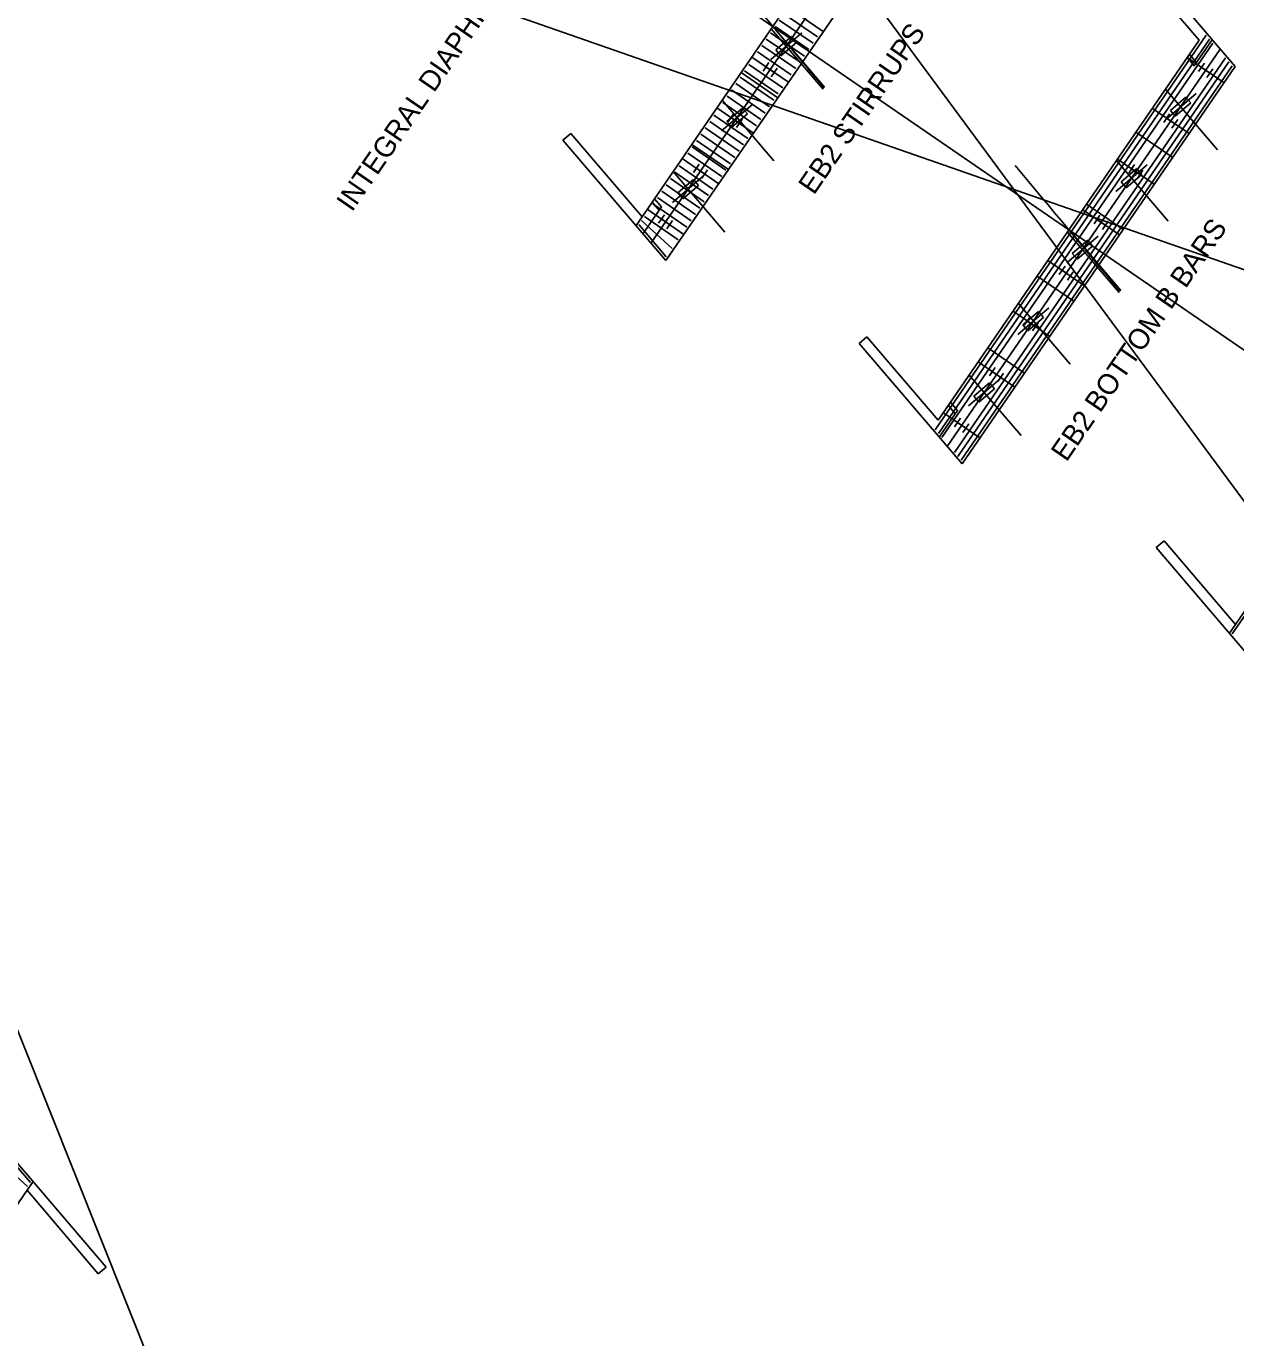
# Model space of a CAD drawing. Extents: x 2378999 to 2381348, y 331302 to 333122.
# Drawn here: x 2379130.1 to 2379248, y 331490.3 to 331618.1 of the extents above; entities that cross this region are included whole.
import ezdxf

# ---------------------------------------------------------------- set-up
doc = ezdxf.new("R2010")
doc.units = 0
for name, color, linetype in [('Arrowhead Terminators', 7, 'Continuous'), ('Arrowhead Terminators CELL', 7, 'Continuous'), ('Dimension Lines', 7, 'Continuous'), ('Dimension Lines CELL', 7, 'Continuous'), ('Mis Work Point CELL', 7, 'Continuous'), ('P_SMU_Bent_Cap', 7, 'Continuous'), ('P_SMU_D_Deck_Outline', 7, 'Continuous'), ('P_SMU_Girder_Concrete', 7, 'Continuous'), ('P_SMU_Mis_L_Lines', 7, 'Continuous'), ('P_SMU_Mis_Long_Chord', 7, 'Continuous'), ('P_SMU_Rebar_B_Bar', 7, 'Continuous'), ('Plan Sheet CELL', 7, 'Continuous'), ('Rebar Lines', 7, 'Continuous'), ('Sup Concrete Slab Lines', 7, 'Continuous')]:
    doc.layers.add(name, color=color, linetype=linetype)

msp = doc.modelspace()

# ---------------------------------------------------------------- linework, layer by layer
at = {"layer": 'Arrowhead Terminators'}
for p, q in [((2379218.72, 331578.81), (2379245.14, 331617.26)), ((2379219.04, 331578.43), (2379245.46, 331616.89)), ((2379219.37, 331578.04), (2379245.79, 331616.49)), ((2379247.02, 331615.05), (2379220.6, 331576.6)), ((2379247.36, 331614.66), (2379220.94, 331576.2)), ((2379247.68, 331614.28), (2379221.26, 331575.83)), ((2379247.69, 331558.9), (2379274.11, 331597.35))]:
    msp.add_line(p, q, dxfattribs=at)
at = {"layer": 'Arrowhead Terminators CELL'}
msp.add_line((2379247.99, 331559.83), (2379247.4, 331558.98), dxfattribs=at)
at = {"layer": 'Dimension Lines'}
for p, q in [((2379316.62, 331479.98), (2379154.62, 331699.5)), ((2379368.09, 331552.83), (2379115.15, 331641.03)), ((2379203.53, 331618.75), (2379206.83, 331616.48)), ((2379203.96, 331619.36), (2379207.25, 331617.1)), ((2379202.68, 331617.51), (2379205.98, 331615.24)), ((2379203.11, 331618.13), (2379206.4, 331615.86)), ((2379201.83, 331616.27), (2379205.13, 331614.01)), ((2379202.26, 331616.89), (2379205.55, 331614.63)), ((2379200.56, 331614.42), (2379203.86, 331612.15)), ((2379201.41, 331615.66), (2379204.7, 331613.39)), ((2379199.71, 331613.18), (2379203.01, 331610.92)), ((2379200.13, 331613.8), (2379203.43, 331611.54)), ((2379198.86, 331611.95), (2379202.16, 331609.68)), ((2379199.28, 331612.56), (2379202.58, 331610.3)), ((2379198.01, 331610.71), (2379201.31, 331608.44)), ((2379198.43, 331611.33), (2379201.73, 331609.06)), ((2379197.16, 331609.47), (2379200.46, 331607.21)), ((2379196.31, 331608.24), (2379199.61, 331605.97)), ((2379196.74, 331608.86), (2379200.03, 331606.59)), ((2379216.61, 331301.94), (2379094.44, 331607.27)), ((2379195.46, 331607), (2379198.76, 331604.74)), ((2379195.89, 331607.62), (2379199.18, 331605.35)), ((2379194.61, 331605.76), (2379197.91, 331603.5)), ((2379195.04, 331606.38), (2379198.33, 331604.12)), ((2379193.76, 331604.53), (2379197.06, 331602.26)), ((2379192.91, 331603.29), (2379196.21, 331601.03)), ((2379193.34, 331603.91), (2379196.64, 331601.65)), ((2379192.06, 331602.06), (2379195.36, 331599.79)), ((2379192.49, 331602.67), (2379195.79, 331600.41)), ((2379191.21, 331600.82), (2379194.51, 331598.55)), ((2379191.64, 331601.44), (2379194.94, 331599.17)), ((2379193.09, 331596.48), (2379190.09, 331599.19)), ((2379190.37, 331599.58), (2379193.66, 331597.32)), ((2379192.51, 331595.65), (2379189.82, 331598.8)), ((2379127.83, 331508.56), (2379130.52, 331505.42)), ((2379127.26, 331507.73), (2379130.25, 331505.02))]:
    msp.add_line(p, q, dxfattribs=at)
at = {"layer": 'Dimension Lines CELL'}
msp.add_line((2379340.37, 331523.67), (2379157.06, 331649.61), dxfattribs=at)
at = {"layer": 'Mis Work Point CELL'}
for p, q in [((2379191.02, 331597.01), (2379217.64, 331635.75)), ((2379219.89, 331577.17), (2379246.51, 331615.91))]:
    msp.add_line(p, q, dxfattribs=at)
at = {"layer": 'P_SMU_Bent_Cap'}
for p, q in [((2379205.73, 331617.5), (2379202.69, 331614.9)), ((2379244.17, 331611.6), (2379241.13, 331609)), ((2379200.94, 331610.53), (2379197.9, 331607.93)), ((2379239.38, 331604.63), (2379236.34, 331602.04)), ((2379196.15, 331603.56), (2379193.11, 331600.96)), ((2379234.6, 331597.67), (2379231.56, 331595.07)), ((2379229.81, 331590.7), (2379226.77, 331588.1)), ((2379225.02, 331583.73), (2379221.98, 331581.13))]:
    msp.add_line(p, q, dxfattribs=at)
at = {"layer": 'P_SMU_D_Deck_Outline'}
for p, q in [((2379204.72, 331617.13), (2379203.2, 331615.83)), ((2379205.21, 331616.56), (2379204.72, 331617.13)), ((2379203.69, 331615.26), (2379203.2, 331615.83)), ((2379205.21, 331616.56), (2379203.69, 331615.26)), ((2379243.17, 331611.24), (2379241.65, 331609.94)), ((2379243.66, 331610.67), (2379242.13, 331609.37)), ((2379243.66, 331610.67), (2379243.17, 331611.24)), ((2379199.94, 331610.17), (2379198.42, 331608.87)), ((2379200.42, 331609.6), (2379198.9, 331608.3)), ((2379200.42, 331609.6), (2379199.94, 331610.17)), ((2379242.13, 331609.37), (2379241.65, 331609.94)), ((2379198.9, 331608.3), (2379198.42, 331608.87)), ((2379238.38, 331604.27), (2379236.86, 331602.97)), ((2379238.87, 331603.7), (2379238.38, 331604.27)), ((2379195.15, 331603.2), (2379193.63, 331601.9)), ((2379195.64, 331602.63), (2379195.15, 331603.2)), ((2379237.35, 331602.4), (2379236.86, 331602.97)), ((2379238.87, 331603.7), (2379237.35, 331602.4)), ((2379194.12, 331601.33), (2379193.63, 331601.9)), ((2379195.64, 331602.63), (2379194.12, 331601.33)), ((2379233.59, 331597.3), (2379232.07, 331596)), ((2379234.08, 331596.73), (2379232.56, 331595.43)), ((2379234.08, 331596.73), (2379233.59, 331597.3)), ((2379232.56, 331595.43), (2379232.07, 331596)), ((2379228.8, 331590.33), (2379227.28, 331589.03)), ((2379229.29, 331589.76), (2379228.8, 331590.33)), ((2379227.77, 331588.46), (2379227.28, 331589.03)), ((2379229.29, 331589.76), (2379227.77, 331588.46)), ((2379224.02, 331583.36), (2379222.5, 331582.06)), ((2379224.5, 331582.79), (2379222.98, 331581.49)), ((2379224.5, 331582.79), (2379224.02, 331583.36)), ((2379222.98, 331581.49), (2379222.5, 331582.06))]:
    msp.add_line(p, q, dxfattribs=at)
at = {"layer": 'P_SMU_Girder_Concrete'}
for p, q in [((2379201.94, 331613.77), (2379202.51, 331614.6)), ((2379244.4, 331613.72), (2379244.97, 331614.54)), ((2379202.23, 331614.18), (2379203.04, 331613.63)), ((2379202.75, 331613.21), (2379203.32, 331614.04)), ((2379244.68, 331614.13), (2379245.5, 331613.57)), ((2379245.21, 331613.16), (2379245.78, 331613.99)), ((2379198.55, 331608.83), (2379199.11, 331609.65)), ((2379241, 331608.77), (2379241.57, 331609.6)), ((2379198.83, 331609.24), (2379199.64, 331608.68)), ((2379199.36, 331608.27), (2379199.92, 331609.09)), ((2379241.29, 331609.19), (2379242.1, 331608.63)), ((2379241.81, 331608.22), (2379242.38, 331609.04)), ((2379195.15, 331603.88), (2379195.71, 331604.7)), ((2379195.43, 331604.29), (2379196.24, 331603.74)), ((2379237.61, 331603.83), (2379238.17, 331604.65)), ((2379237.89, 331604.24), (2379238.7, 331603.68)), ((2379195.96, 331603.32), (2379196.52, 331604.15)), ((2379238.42, 331603.27), (2379238.98, 331604.1)), ((2379191.75, 331598.94), (2379192.32, 331599.76)), ((2379192.03, 331599.35), (2379192.84, 331598.79)), ((2379192.56, 331598.38), (2379193.13, 331599.2)), ((2379234.21, 331598.88), (2379234.77, 331599.71)), ((2379234.49, 331599.29), (2379235.3, 331598.74)), ((2379235.02, 331598.33), (2379235.59, 331599.15)), ((2379230.81, 331593.94), (2379231.38, 331594.76)), ((2379231.09, 331594.35), (2379231.9, 331593.79)), ((2379231.62, 331593.38), (2379232.19, 331594.2)), ((2379227.41, 331588.99), (2379227.98, 331589.82)), ((2379227.7, 331589.4), (2379228.51, 331588.85)), ((2379228.22, 331588.44), (2379228.79, 331589.26)), ((2379224.02, 331584.05), (2379224.58, 331584.87)), ((2379224.3, 331584.46), (2379225.11, 331583.9)), ((2379224.83, 331583.49), (2379225.39, 331584.31)), ((2379220.62, 331579.1), (2379221.18, 331579.93)), ((2379220.9, 331579.51), (2379221.71, 331578.96)), ((2379221.43, 331578.54), (2379221.99, 331579.37))]:
    msp.add_line(p, q, dxfattribs=at)
at = {"layer": 'P_SMU_Mis_L_Lines'}
for p, q in [((2379207.8, 331612), (2379202.75, 331617.9)), ((2379246.24, 331606.1), (2379241.19, 331612.01)), ((2379203.01, 331605.03), (2379197.96, 331610.94)), ((2379241.45, 331599.14), (2379236.41, 331605.04)), ((2379198.22, 331598.06), (2379193.18, 331603.97)), ((2379236.66, 331592.17), (2379231.62, 331598.07)), ((2379231.88, 331585.2), (2379226.83, 331591.1)), ((2379227.09, 331578.23), (2379222.04, 331584.13))]:
    msp.add_line(p, q, dxfattribs=at)
at = {"layer": 'P_SMU_Mis_Long_Chord'}
for centre in [(2384635.84, 336157.89), (2384664.71, 336138.05)]:
    msp.add_arc(centre, 7080, 219.816017, 219.945167, dxfattribs=at)
at = {"layer": 'P_SMU_Rebar_B_Bar'}
for p, q in [((2379215.59, 331636.6), (2379190.15, 331599.57)), ((2379219.09, 331634.04), (2379192.48, 331595.3)), ((2379247.96, 331614.21), (2379237.93, 331625.95)), ((2379244.46, 331616.77), (2379237.17, 331625.31)), ((2379244.46, 331616.77), (2379219.02, 331579.73)), ((2379245.72, 331616.83), (2379243.97, 331614.29)), ((2379203.38, 331611.17), (2379199.81, 331613.62)), ((2379247.96, 331614.21), (2379221.35, 331575.47)), ((2379183.2, 331607.7), (2379182.44, 331607.05)), ((2379192.48, 331595.3), (2379182.44, 331607.05)), ((2379190.15, 331599.57), (2379183.2, 331607.7)), ((2379241.88, 331605.35), (2379238.3, 331607.8)), ((2379198.57, 331604.16), (2379195, 331606.62)), ((2379190.24, 331597.93), (2379192.03, 331600.53)), ((2379237.06, 331598.34), (2379233.49, 331600.8)), ((2379189.57, 331598.71), (2379190.15, 331599.57)), ((2379273.43, 331596.86), (2379247.99, 331559.83)), ((2379232.25, 331591.34), (2379228.68, 331593.79)), ((2379212.07, 331587.87), (2379211.31, 331587.22)), ((2379219.02, 331579.73), (2379212.07, 331587.87)), ((2379221.35, 331575.47), (2379211.31, 331587.22)), ((2379227.44, 331584.33), (2379223.86, 331586.78)), ((2379219.11, 331578.09), (2379220.89, 331580.69)), ((2379241.04, 331567.96), (2379240.28, 331567.31)), ((2379250.32, 331555.57), (2379240.28, 331567.31)), ((2379247.99, 331559.83), (2379241.04, 331567.96)), ((2379127.87, 331508.91), (2379137.9, 331497.16)), ((2379130.19, 331504.65), (2379104.75, 331467.61)), ((2379130.19, 331504.65), (2379130.78, 331505.5)), ((2379130.19, 331504.65), (2379137.14, 331496.51)), ((2379137.14, 331496.51), (2379137.9, 331497.16))]:
    msp.add_line(p, q, dxfattribs=at)
for points in [[(2379243.53, 331615.4), (2379244.19, 331614.61), (2379243.97, 331614.29), (2379243.31, 331615.08)], [(2379191.36, 331601.32), (2379192.03, 331600.53), (2379191.8, 331600.21), (2379191.14, 331601)], [(2379220.23, 331581.49), (2379220.89, 331580.69), (2379220.67, 331580.37), (2379220.01, 331581.17)]]:
    msp.add_lwpolyline(points, close=True, dxfattribs=at)
for centre, radius, start, end in [((2384664.71, 336138.05), 7060.38, 219.837589, 219.846018), ((2384635.84, 336157.89), 7100, 219.927282, 219.935659), ((2384635.84, 336157.89), 7099.63, 219.926438, 219.934816), ((2384664.71, 336138.05), 7099.63, 219.926438, 219.934816)]:
    msp.add_arc(centre, radius, start, end, dxfattribs=at)
at = {"layer": 'Plan Sheet CELL'}
for p, q in [((2379207.94, 331612.21), (2379202.9, 331618.12)), ((2379236.81, 331592.38), (2379231.77, 331598.28))]:
    msp.add_line(p, q, dxfattribs=at)
at = {"layer": 'Rebar Lines'}
for p, q in [((2379207.81, 331617.62), (2379204.24, 331620.08)), ((2379204.42, 331612.68), (2379200.85, 331615.13)), ((2379246.88, 331612.63), (2379243.3, 331615.08)), ((2379201.02, 331607.73), (2379197.45, 331610.19)), ((2379243.48, 331607.68), (2379239.91, 331610.13)), ((2379197.62, 331602.79), (2379194.05, 331605.24)), ((2379240.08, 331602.73), (2379236.51, 331605.19)), ((2379194.22, 331597.84), (2379190.65, 331600.3)), ((2379236.68, 331597.79), (2379233.11, 331600.24)), ((2379233.29, 331592.84), (2379229.71, 331595.3)), ((2379229.89, 331587.9), (2379226.32, 331590.35)), ((2379226.49, 331582.95), (2379222.92, 331585.41)), ((2379223.09, 331578.01), (2379219.52, 331580.46))]:
    msp.add_line(p, q, dxfattribs=at)

# ---------------------------------------------------------------- texts
at = {"layer": 'Sup Concrete Slab Lines'}
for s, p in [('INTEGRAL DIAPHRAGM U & CAP V BARS @ EB2', (2379161.87, 331599.96)), ('EB2 STIRRUPS', (2379206.9, 331601.61)), ('EB2 BOTTOM B BARS', (2379231.52, 331575.59))]:
    msp.add_text(s, height=2, rotation=55.5093, dxfattribs=at).set_placement(p)

doc.saveas('drawing.dxf')
